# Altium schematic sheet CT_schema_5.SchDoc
size 224 x 182 mm
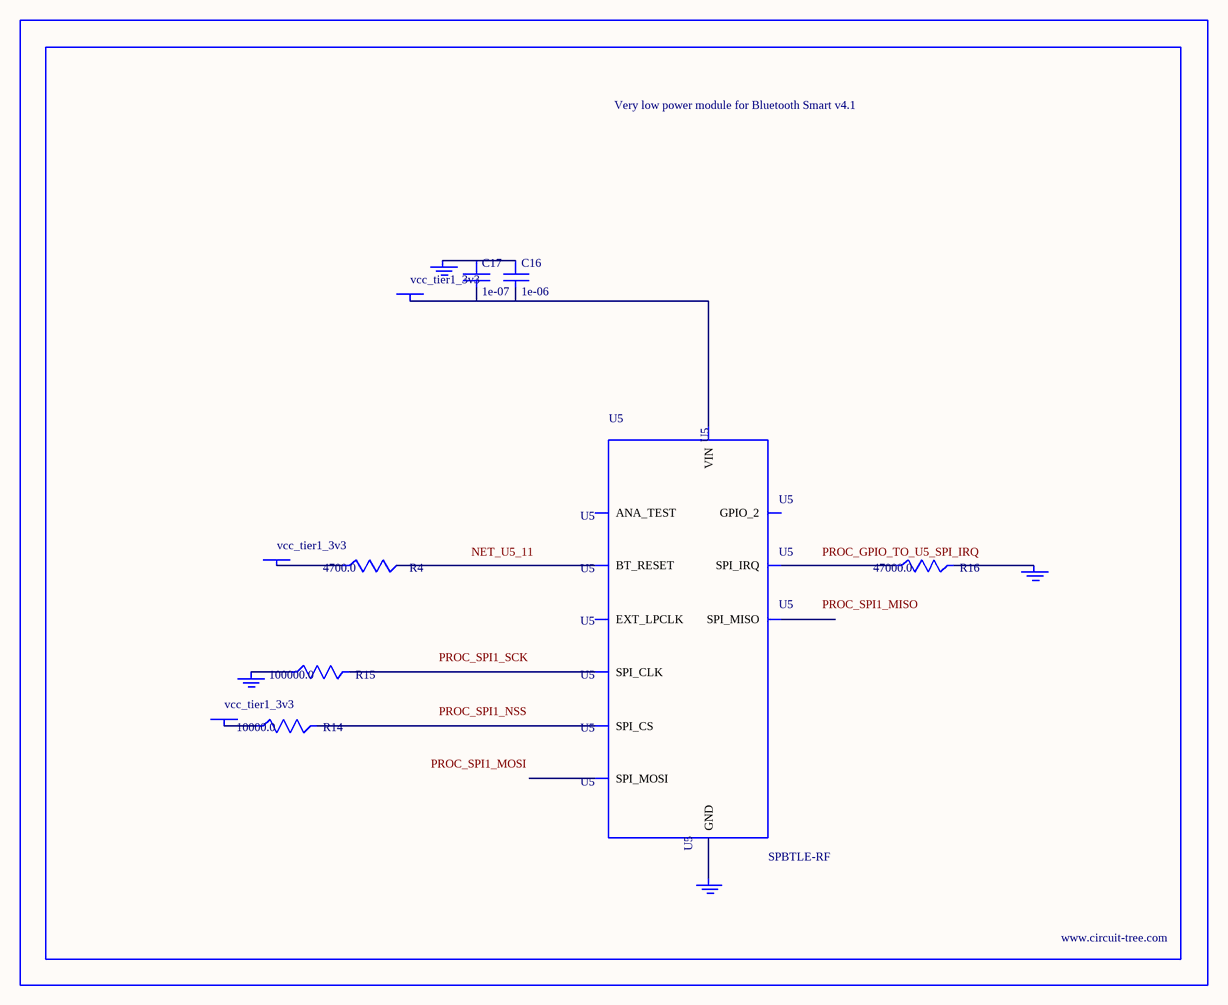
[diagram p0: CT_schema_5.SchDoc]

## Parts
BORDER4  (no value)
C16  1e-06  [C0603]
C17  1e-07  [C0402]
GND_INSTANCE_4_0  (no value)
GND_INSTANCE_4_1  (no value)
GND_INSTANCE_4_2  (no value)
GND_INSTANCE_4_3  (no value)
POWER_INSTANCE_4_0  vcc_tier1_3v3
POWER_INSTANCE_4_1  vcc_tier1_3v3
POWER_INSTANCE_4_2  vcc_tier1_3v3
R4  4700.0  [R0603]
R14  10000.0  [R0603]
R15  100000.0  [R0603]
R16  47000.0  [R0603]
U5  SPBTLE-RF  [XCVR_SPBTLE-RF]

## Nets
NetC16_1: C16.1 C17.1 GND_INSTANCE_4_1.0(GND)
NetC16_2: C16.2 C17.2 POWER_INSTANCE_4_0.0(PWR) U5.5(VIN)
NetGND_INSTANCE_4_0_0: GND_INSTANCE_4_0.0(GND) R16.2
NetGND_INSTANCE_4_2_0: GND_INSTANCE_4_2.0(GND) R15.1
NetGND_INSTANCE_4_3_0: GND_INSTANCE_4_3.0(GND) U5.6(GND)
NetPOWER_INSTANCE_4_1_0: POWER_INSTANCE_4_1.0(PWR) R14.1
NetPOWER_INSTANCE_4_2_0: POWER_INSTANCE_4_2.0(PWR) R4.1
NetR4_2: R4.2 U5.11(BT_RESET)
NetR14_2: R14.2 U5.10(SPI_CS)
NetR15_2: R15.2 U5.7(SPI_CLK)
NetR16_1: R16.1 U5.4(SPI_IRQ)

Not connected (* = marked no-connect by the designer): U5 1(EXT_LPCLK) 2(GPIO_2) 3(ANA_TEST) 8(SPI_MISO) 9(SPI_MOSI)

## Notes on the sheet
- Labels drawn without touching a wire or pin: NET_U5_11, PROC_GPIO_TO_U5_SPI_IRQ, PROC_SPI1_MISO, PROC_SPI1_MOSI, PROC_SPI1_NSS, PROC_SPI1_SCK

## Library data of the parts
BORDER4 = BORDER_PAGE4
C16 = C0603C105K3RACTU
C17 = C0402C104K3RACTU
GND_INSTANCE_4_0-GND_INSTANCE_4_3 = GND
POWER_INSTANCE_4_0-POWER_INSTANCE_4_2 = PWR
R4 = RC0603JR-074K7L
R14 = RC0603JR-0710KL
R15 = RC0603JR-07100KL
R16 = RC0603JR-0747KL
